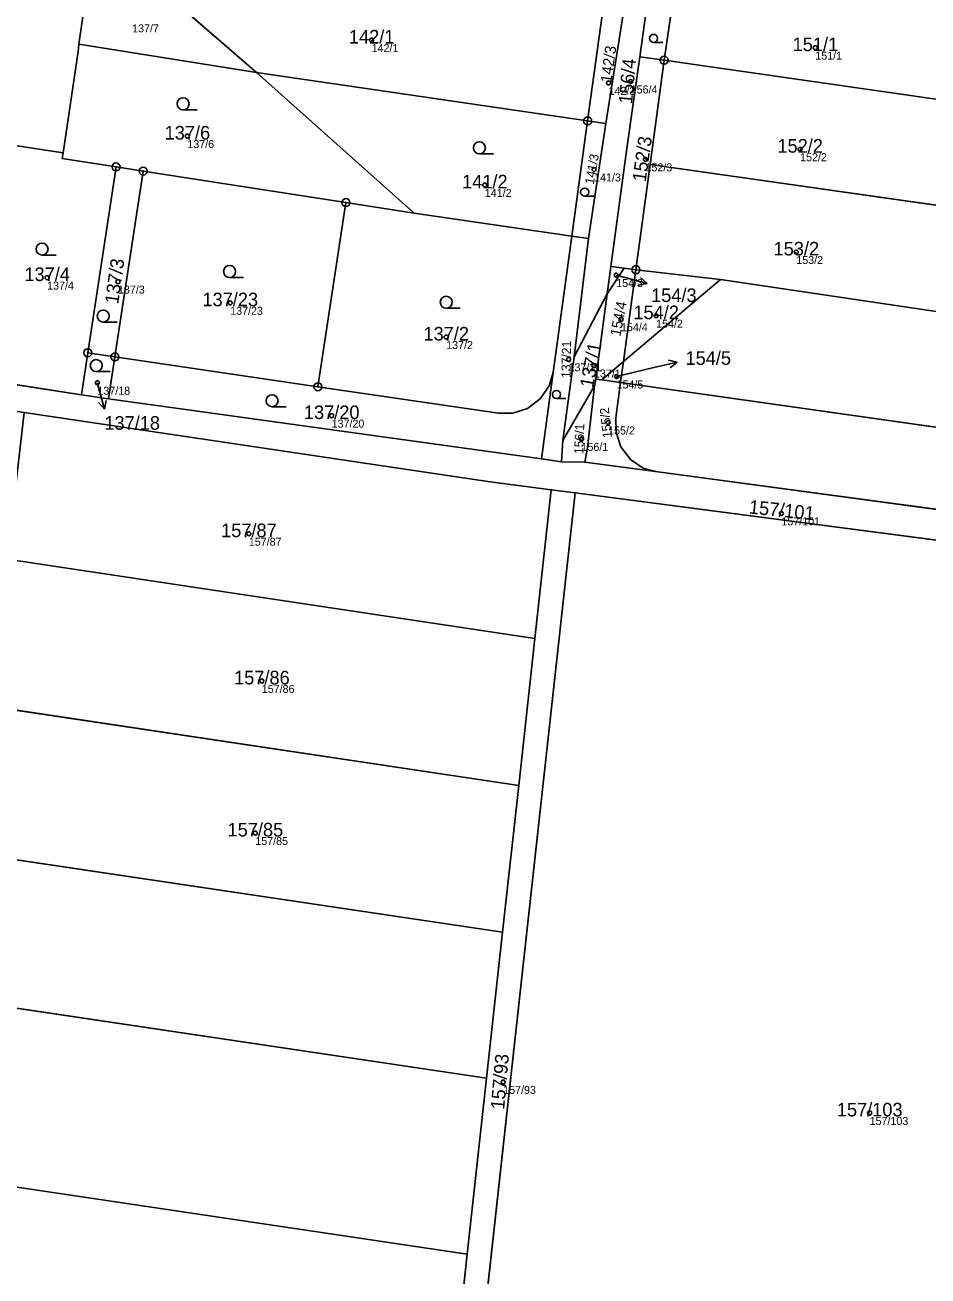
# Model space of a CAD drawing. Extents: x -603967 to -594699, y -1179315 to -1165625.
# Drawn here: x -598435.3 to -598322.4, y -1172798.3 to -1172641.9 of the extents above; entities that cross this region are included whole.
import ezdxf

# ---------------------------------------------------------------- set-up
doc = ezdxf.new("R2010")
doc.units = 0
for name, color, linetype in [('Definiční body', 7, 'Continuous'), ('Hranice parcel', 7, 'Continuous'), ('Parcelní čísla', 7, 'Continuous'), ('Polygon parcely', 7, 'Continuous'), ('Pop  PČ popisy', 7, 'Continuous'), ('Značky bodu BP', 7, 'Continuous'), ('Značky kultur', 7, 'Continuous')]:
    doc.layers.add(name, color=color, linetype=linetype)

msp = doc.modelspace()

# ---------------------------------------------------------------- linework, layer by layer
at = {"layer": 'Definiční body'}
for centre in [(-598391.99, -1172643.83994), (-598336.52, -1172644.78994), (-598362.37, -1172649.18994), (-598359.6, -1172649.01994), (-598415.03, -1172655.83994), (-598357.75, -1172658.74994), (-598338.42, -1172657.47994), (-598364.17, -1172660.00994), (-598377.84, -1172661.94994), (-598338.9, -1172670.32994), (-598432.56, -1172673.52994), (-598423.7, -1172674.02994), (-598361.41, -1172673.20994), (-598409.67, -1172676.67994), (-598360.81, -1172678.72994), (-598356.42, -1172678.28994), (-598382.67, -1172680.95994), (-598367.37, -1172683.74994), (-598364.19, -1172684.51994), (-598426.27, -1172686.66994), (-598361.37, -1172685.88994), (-598396.99, -1172690.77994), (-598362.42, -1172691.63994), (-598365.75, -1172693.68994), (-598340.76, -1172702.99994), (-598407.34, -1172705.53994), (-598405.72, -1172723.93994), (-598406.53, -1172742.94994), (-598375.54, -1172774.05994), (-598329.73, -1172777.93994)]:
    msp.add_circle(centre, 0.25, dxfattribs=at)
at = {"layer": 'Hranice parcel'}
for p, q in [((-598426.71, -1172630.26), (-598406.37, -1172647.87)), ((-598358.46, -1172645.91), (-598356.86, -1172634.46)), ((-598353.75, -1172634.89), (-598355.42, -1172646.35)), ((-598364.98, -1172653.93), (-598362.96, -1172639.21)), ((-598360.39, -1172639.57), (-598362.72, -1172654.26)), ((-598406.37, -1172647.87), (-598428.58, -1172644.33)), ((-598358.46, -1172645.91), (-598360.09, -1172657.4)), ((-598355.42, -1172646.35), (-598358.46, -1172645.91)), ((-598355.42, -1172646.35), (-598357.17, -1172659.37)), ((-598355.42, -1172646.35), (-598319.41, -1172651.51)), ((-598364.98, -1172653.93), (-598406.37, -1172647.87)), ((-598406.37, -1172647.87), (-598386.67, -1172665.48)), ((-598366.97, -1172668.32), (-598364.98, -1172653.93)), ((-598362.72, -1172654.26), (-598364.98, -1172653.93)), ((-598362.72, -1172654.26), (-598364.86, -1172668.62)), ((-598430.55, -1172657.92), (-598436.61, -1172656.99)), ((-598360.09, -1172657.4), (-598362.07, -1172672.12)), ((-598423.94, -1172659.69), (-598427.47, -1172682.92)), ((-598420.55, -1172660.21), (-598423.94, -1172659.69)), ((-598358.94, -1172672.53), (-598357.17, -1172659.37)), ((-598357.17, -1172659.37), (-598313.73, -1172665.56)), ((-598424.08, -1172683.44), (-598420.55, -1172660.21)), ((-598420.55, -1172660.21), (-598395.2, -1172664.15)), ((-598395.2, -1172664.15), (-598398.7, -1172687.17)), ((-598386.67, -1172665.48), (-598395.2, -1172664.15)), ((-598386.67, -1172665.48), (-598366.97, -1172668.32)), ((-598369.29, -1172685.37), (-598366.97, -1172668.32)), ((-598364.86, -1172668.62), (-598366.97, -1172668.32)), ((-598364.86, -1172668.62), (-598366.68, -1172683.42)), ((-598362.07, -1172672.12), (-598362.53, -1172675.55)), ((-598362.53, -1172675.55), (-598360.42, -1172672.36)), ((-598362.07, -1172672.12), (-598360.42, -1172672.36)), ((-598358.94, -1172672.53), (-598360.51, -1172684.01)), ((-598360.42, -1172672.36), (-598358.94, -1172672.53)), ((-598358.94, -1172672.53), (-598348.38, -1172673.77)), ((-598348.38, -1172673.77), (-598360.51, -1172684.01)), ((-598348.38, -1172673.77), (-598315.49, -1172678.65)), ((-598366.68, -1172683.42), (-598362.53, -1172675.55)), ((-598363.95, -1172686.2), (-598362.53, -1172675.55)), ((-598428.27, -1172688.16), (-598427.47, -1172682.92)), ((-598427.47, -1172682.92), (-598424.08, -1172683.44)), ((-598424.88, -1172688.67), (-598424.08, -1172683.44)), ((-598398.7, -1172687.17), (-598424.08, -1172683.44)), ((-598366.68, -1172683.42), (-598368.08, -1172693.89)), ((-598363.22, -1172686.3), (-598360.51, -1172684.01)), ((-598360.51, -1172684.01), (-598360.86, -1172686.63)), ((-598428.27, -1172688.16), (-598441.07, -1172686.19)), ((-598369.29, -1172685.37), (-598370.77, -1172696.19)), ((-598364.11, -1172687.05), (-598363.95, -1172686.2)), ((-598363.95, -1172686.2), (-598363.22, -1172686.3)), ((-598360.86, -1172686.63), (-598363.22, -1172686.3)), ((-598360.86, -1172686.63), (-598361.47, -1172691.06)), ((-598360.86, -1172686.63), (-598274.9, -1172698.81)), ((-598424.88, -1172688.67), (-598428.27, -1172688.16)), ((-598364.11, -1172687.05), (-598368.08, -1172693.89)), ((-598370.77, -1172696.19), (-598424.88, -1172688.67)), ((-598368.08, -1172693.89), (-598368.26, -1172696.54)), ((-598370.77, -1172696.19), (-598368.26, -1172696.54)), ((-598368.26, -1172696.54), (-598365.33, -1172696.58)), ((-598365.33, -1172696.58), (-598356.5, -1172697.77)), ((-598358.03, -1172697.32), (-598356.5, -1172697.77)), ((-598356.5, -1172697.77), (-598281.7, -1172707.81)), ((-598381.45, -1172835.83), (-598366.56, -1172700.44)), ((-598371.58, -1172718.62), (-598369.53, -1172700.04)), ((-598366.56, -1172700.44), (-598369.53, -1172700.04)), ((-598366.56, -1172700.44), (-598273.19, -1172712.63)), ((-598371.58, -1172718.62), (-598437.54, -1172708.73)), ((-598373.59, -1172737), (-598371.58, -1172718.62)), ((-598373.59, -1172737), (-598439.67, -1172727.11)), ((-598375.62, -1172755.34), (-598373.59, -1172737)), ((-598375.62, -1172755.34), (-598441.79, -1172745.48)), ((-598377.62, -1172773.59), (-598504.56, -1172754.7)), ((-598377.62, -1172773.59), (-598375.62, -1172755.34)), ((-598380.04, -1172795.58), (-598377.62, -1172773.59)), ((-598380.04, -1172795.58), (-598492.64, -1172778.82)), ((-598383.06, -1172823.11), (-598380.04, -1172795.58))]:
    msp.add_line(p, q, dxfattribs=at)
for points in [[(-598427.99, -1172640.29), (-598428.16, -1172641.47), (-598428.58, -1172644.33)], [(-598428.58, -1172644.33), (-598428.69, -1172645.28), (-598430.55, -1172657.92)], [(-598423.94, -1172659.69), (-598430.66, -1172658.65), (-598430.55, -1172657.92)], [(-598398.7, -1172687.17), (-598376.12, -1172690.48), (-598374.34, -1172690.48), (-598372.5, -1172689.88), (-598370.9, -1172688.69), (-598369.79, -1172687.06), (-598369.29, -1172685.37)], [(-598365.33, -1172696.58), (-598364.99, -1172694.76), (-598364.11, -1172687.05)], [(-598369.53, -1172700.04), (-598377.46, -1172699.01), (-598435.42, -1172690.36)], [(-598361.47, -1172691.06), (-598361.43, -1172692.84), (-598360.82, -1172694.66), (-598359.62, -1172696.25), (-598358.03, -1172697.32)]]:
    msp.add_lwpolyline(points, dxfattribs=at)
at = {"layer": 'Polygon parcely'}
for points in [[(-598355.28, -1172623.09), (-598354, -1172612.83), (-598352.45, -1172601.73), (-598351.3, -1172595.7), (-598354.22, -1172595.25), (-598355.96, -1172610.07), (-598358.38, -1172624.41), (-598360.39, -1172639.57), (-598362.72, -1172654.26), (-598364.86, -1172668.62), (-598366.68, -1172683.42), (-598362.53, -1172675.55), (-598362.07, -1172672.12), (-598360.09, -1172657.4), (-598358.46, -1172645.91), (-598356.86, -1172634.46)], [(-598490.98, -1172630.62), (-598493.49, -1172630.23), (-598493.67, -1172631.41), (-598496.35, -1172647.82), (-598436.61, -1172656.99), (-598430.55, -1172657.92), (-598428.69, -1172645.28), (-598428.58, -1172644.33), (-598428.16, -1172641.47), (-598427.99, -1172640.29)], [(-598427.99, -1172640.29), (-598428.16, -1172641.47), (-598428.58, -1172644.33), (-598406.37, -1172647.87), (-598426.71, -1172630.26)], [(-598364.98, -1172653.93), (-598362.96, -1172639.21), (-598426.71, -1172630.26), (-598406.37, -1172647.87)], [(-598353.75, -1172634.89), (-598356.86, -1172634.46), (-598358.46, -1172645.91), (-598355.42, -1172646.35)], [(-598353.75, -1172634.89), (-598355.42, -1172646.35), (-598319.41, -1172651.51), (-598298.94, -1172642.4), (-598309.94, -1172640.89)], [(-598360.39, -1172639.57), (-598362.96, -1172639.21), (-598364.98, -1172653.93), (-598362.72, -1172654.26)], [(-598395.2, -1172664.15), (-598386.67, -1172665.48), (-598406.37, -1172647.87), (-598428.58, -1172644.33), (-598428.69, -1172645.28), (-598430.55, -1172657.92), (-598430.66, -1172658.65), (-598423.94, -1172659.69), (-598420.55, -1172660.21)], [(-598358.46, -1172645.91), (-598360.09, -1172657.4), (-598362.07, -1172672.12), (-598360.42, -1172672.36), (-598358.94, -1172672.53), (-598357.17, -1172659.37), (-598355.42, -1172646.35)], [(-598357.17, -1172659.37), (-598313.73, -1172665.56), (-598311.98, -1172652.51), (-598319.41, -1172651.51), (-598355.42, -1172646.35)], [(-598364.98, -1172653.93), (-598406.37, -1172647.87), (-598386.67, -1172665.48), (-598366.97, -1172668.32)], [(-598364.98, -1172653.93), (-598366.97, -1172668.32), (-598364.86, -1172668.62), (-598362.72, -1172654.26)], [(-598428.27, -1172688.16), (-598427.47, -1172682.92), (-598423.94, -1172659.69), (-598430.66, -1172658.65), (-598430.55, -1172657.92), (-598436.61, -1172656.99), (-598441.07, -1172686.19)], [(-598424.08, -1172683.44), (-598420.55, -1172660.21), (-598423.94, -1172659.69), (-598427.47, -1172682.92)], [(-598315.49, -1172678.65), (-598313.73, -1172665.56), (-598357.17, -1172659.37), (-598358.94, -1172672.53), (-598348.38, -1172673.77)], [(-598398.7, -1172687.17), (-598395.2, -1172664.15), (-598420.55, -1172660.21), (-598424.08, -1172683.44)], [(-598398.7, -1172687.17), (-598376.12, -1172690.48), (-598374.34, -1172690.48), (-598372.5, -1172689.88), (-598370.9, -1172688.69), (-598369.79, -1172687.06), (-598369.29, -1172685.37), (-598366.97, -1172668.32), (-598386.67, -1172665.48), (-598395.2, -1172664.15)], [(-598364.86, -1172668.62), (-598366.97, -1172668.32), (-598369.29, -1172685.37), (-598370.77, -1172696.19), (-598368.26, -1172696.54), (-598368.08, -1172693.89), (-598366.68, -1172683.42)], [(-598363.22, -1172686.3), (-598360.51, -1172684.01), (-598358.94, -1172672.53), (-598360.42, -1172672.36), (-598362.53, -1172675.55), (-598363.95, -1172686.2)], [(-598362.53, -1172675.55), (-598360.42, -1172672.36), (-598362.07, -1172672.12)], [(-598358.94, -1172672.53), (-598360.51, -1172684.01), (-598348.38, -1172673.77)], [(-598274.9, -1172698.81), (-598272.85, -1172684.97), (-598315.49, -1172678.65), (-598348.38, -1172673.77), (-598360.51, -1172684.01), (-598360.86, -1172686.63)], [(-598363.95, -1172686.2), (-598362.53, -1172675.55), (-598366.68, -1172683.42), (-598368.08, -1172693.89), (-598364.11, -1172687.05)], [(-598501.79, -1172680.45), (-598435.42, -1172690.36), (-598377.46, -1172699.01), (-598369.53, -1172700.04), (-598366.56, -1172700.44), (-598273.19, -1172712.63), (-598267.08, -1172713.02), (-598266.58, -1172710.18), (-598269.53, -1172709.44), (-598281.7, -1172707.81), (-598356.5, -1172697.77), (-598365.33, -1172696.58), (-598368.26, -1172696.54), (-598370.77, -1172696.19), (-598424.88, -1172688.67), (-598428.27, -1172688.16), (-598441.07, -1172686.19), (-598501.04, -1172676.88)], [(-598424.88, -1172688.67), (-598424.08, -1172683.44), (-598427.47, -1172682.92), (-598428.27, -1172688.16)], [(-598398.7, -1172687.17), (-598424.08, -1172683.44), (-598424.88, -1172688.67), (-598370.77, -1172696.19), (-598369.29, -1172685.37), (-598369.79, -1172687.06), (-598370.9, -1172688.69), (-598372.5, -1172689.88), (-598374.34, -1172690.48), (-598376.12, -1172690.48)], [(-598360.86, -1172686.63), (-598360.51, -1172684.01), (-598363.22, -1172686.3)], [(-598360.86, -1172686.63), (-598363.22, -1172686.3), (-598363.95, -1172686.2), (-598364.11, -1172687.05), (-598364.99, -1172694.76), (-598365.33, -1172696.58), (-598356.5, -1172697.77), (-598358.03, -1172697.32), (-598359.62, -1172696.25), (-598360.82, -1172694.66), (-598361.43, -1172692.84), (-598361.47, -1172691.06)], [(-598356.5, -1172697.77), (-598281.7, -1172707.81), (-598280.42, -1172707.77), (-598278.62, -1172707.16), (-598277.08, -1172705.91), (-598275.97, -1172704.31), (-598275.47, -1172702.5), (-598274.9, -1172698.81), (-598360.86, -1172686.63), (-598361.47, -1172691.06), (-598361.43, -1172692.84), (-598360.82, -1172694.66), (-598359.62, -1172696.25), (-598358.03, -1172697.32)], [(-598364.11, -1172687.05), (-598368.08, -1172693.89), (-598368.26, -1172696.54), (-598365.33, -1172696.58), (-598364.99, -1172694.76)], [(-598437.54, -1172708.73), (-598371.58, -1172718.62), (-598369.53, -1172700.04), (-598377.46, -1172699.01), (-598435.42, -1172690.36), (-598437.44, -1172707.81)], [(-598387.22, -1172888.4), (-598385.83, -1172875.74), (-598384.37, -1172862.43), (-598381.45, -1172835.83), (-598366.56, -1172700.44), (-598369.53, -1172700.04), (-598371.58, -1172718.62), (-598373.59, -1172737), (-598375.62, -1172755.34), (-598377.62, -1172773.59), (-598380.04, -1172795.58), (-598383.06, -1172823.11), (-598386.27, -1172852.23), (-598388.21, -1172869.98), (-598391.58, -1172900.59), (-598392.59, -1172909.8), (-598389.59, -1172910.18)], [(-598381.45, -1172835.83), (-598284.95, -1172847.74), (-598270.45, -1172715.99), (-598273.19, -1172712.63), (-598366.56, -1172700.44)], [(-598439.51, -1172725.76), (-598439.67, -1172727.11), (-598373.59, -1172737), (-598371.58, -1172718.62), (-598437.54, -1172708.73)], [(-598373.59, -1172737), (-598439.67, -1172727.11), (-598441.79, -1172745.48), (-598375.62, -1172755.34)], [(-598509.23, -1172735.44), (-598504.56, -1172754.7), (-598377.62, -1172773.59), (-598375.62, -1172755.34), (-598441.79, -1172745.48)], [(-598380.04, -1172795.58), (-598377.62, -1172773.59), (-598504.56, -1172754.7), (-598504.46, -1172755.12), (-598492.64, -1172778.82)], [(-598380.04, -1172795.58), (-598492.64, -1172778.82), (-598477.56, -1172809.04), (-598383.06, -1172823.11)]]:
    msp.add_lwpolyline(points, close=True, dxfattribs=at)
at = {"layer": 'Pop  PČ popisy'}
for p, q in [((-598361.41, -1172673.21), (-598360.45, -1172673.47)), ((-598360.45, -1172673.47), (-598357.551, -1172674.247)), ((-598357.551, -1172674.247), (-598358.389, -1172673.504)), ((-598357.551, -1172674.247), (-598358.648, -1172674.471)), ((-598361.37, -1172685.89), (-598356.71, -1172684.77)), ((-598356.71, -1172684.77), (-598353.786, -1172684.095)), ((-598353.786, -1172684.095), (-598354.874, -1172683.832)), ((-598353.786, -1172684.095), (-598354.649, -1172684.808)), ((-598426.27, -1172686.67), (-598426.17, -1172687.07)), ((-598426.17, -1172687.07), (-598425.393, -1172689.969)), ((-598425.393, -1172689.969), (-598426.136, -1172689.131)), ((-598425.393, -1172689.969), (-598425.169, -1172688.872))]:
    msp.add_line(p, q, dxfattribs=at)
at = {"layer": 'Značky bodu BP'}
for centre, radius in [((-598355.42, -1172646.34988), 0.5), ((-598355.42, -1172646.34988), 0.0303), ((-598364.98, -1172653.92988), 0.5), ((-598364.98, -1172653.92988), 0.0303), ((-598423.94, -1172659.68988), 0.5), ((-598423.94, -1172659.68988), 0.0303), ((-598420.55, -1172660.20988), 0.5), ((-598420.55, -1172660.20988), 0.0303), ((-598395.2, -1172664.14988), 0.5), ((-598395.2, -1172664.14988), 0.0303), ((-598358.94, -1172672.52988), 0.5), ((-598358.94, -1172672.52988), 0.0303), ((-598427.47, -1172682.91988), 0.5), ((-598427.47, -1172682.91988), 0.0303), ((-598424.08, -1172683.43988), 0.5), ((-598424.08, -1172683.43988), 0.0303), ((-598398.7, -1172687.16988), 0.5), ((-598398.7, -1172687.16988), 0.0303)]:
    msp.add_circle(centre, radius, dxfattribs=at)
at = {"layer": 'Značky kultur'}
for p, q in [((-598356.735, -1172644.12), (-598355.563, -1172644.12)), ((-598415.553, -1172652.55), (-598413.803, -1172652.55)), ((-598378.513, -1172658.05), (-598376.763, -1172658.05)), ((-598365.355, -1172663.34), (-598364.183, -1172663.34)), ((-598433.193, -1172670.7), (-598431.443, -1172670.7)), ((-598409.753, -1172673.51), (-598408.003, -1172673.51)), ((-598382.663, -1172677.36), (-598380.913, -1172677.36)), ((-598425.543, -1172679.07), (-598423.793, -1172679.07)), ((-598426.413, -1172685.26), (-598424.663, -1172685.26)), ((-598404.443, -1172689.66), (-598402.693, -1172689.66)), ((-598368.875, -1172688.64), (-598367.703, -1172688.64))]:
    msp.add_line(p, q, dxfattribs=at)
for centre, radius in [((-598356.73521, -1172643.61737), 0.5025), ((-598415.55286, -1172651.79981), 0.75), ((-598378.51286, -1172657.29981), 0.75), ((-598365.35521, -1172662.83737), 0.5025), ((-598433.19286, -1172669.94981), 0.75), ((-598409.75286, -1172672.75981), 0.75), ((-598382.66286, -1172676.60981), 0.75), ((-598425.54286, -1172678.31981), 0.75), ((-598426.41286, -1172684.50981), 0.75), ((-598404.44286, -1172688.90981), 0.75), ((-598368.87521, -1172688.13737), 0.5025)]:
    msp.add_circle(centre, radius, dxfattribs=at)

# ---------------------------------------------------------------- texts
at = {"layer": 'Definiční body'}
for s, p in [('137/7', (-598421.93, -1172642.869)), ('142/1', (-598391.99, -1172645.329)), ('151/1', (-598336.52, -1172646.279)), ('142/3', (-598362.37, -1172650.679)), ('156/4', (-598359.6, -1172650.509)), ('137/6', (-598415.03, -1172657.329)), ('152/2', (-598338.42, -1172658.969)), ('152/3', (-598357.75, -1172660.239)), ('141/3', (-598364.17, -1172661.499)), ('141/2', (-598377.84, -1172663.439)), ('153/2', (-598338.9, -1172671.819)), ('137/4', (-598432.56, -1172675.019)), ('154/3', (-598361.41, -1172674.699)), ('137/3', (-598423.7, -1172675.519)), ('137/23', (-598409.67, -1172678.169)), ('154/2', (-598356.42, -1172679.779)), ('154/4', (-598360.81, -1172680.219)), ('137/2', (-598382.67, -1172682.449)), ('137/21', (-598367.37, -1172685.239)), ('137/1', (-598364.19, -1172686.009)), ('154/5', (-598361.37, -1172687.379)), ('137/18', (-598426.27, -1172688.159)), ('137/20', (-598396.99, -1172692.269)), ('155/2', (-598362.42, -1172693.129)), ('156/1', (-598365.75, -1172695.179)), ('157/101', (-598340.76, -1172704.489)), ('157/87', (-598407.34, -1172707.029)), ('157/86', (-598405.72, -1172725.429)), ('157/85', (-598406.53, -1172744.439)), ('157/93', (-598375.54, -1172775.549)), ('157/103', (-598329.73, -1172779.429))]:
    msp.add_text(s, height=0.999996, dxfattribs=at).set_placement(p)
at = {"layer": 'Parcelní čísla'}
for s, p in [('142/1', (-598394.826, -1172644.265)), ('151/1', (-598339.356, -1172645.215)), ('137/6', (-598417.866, -1172656.265)), ('152/2', (-598341.256, -1172657.905)), ('141/2', (-598380.676, -1172662.375)), ('153/2', (-598341.736, -1172670.755)), ('137/4', (-598435.396, -1172673.955)), ('137/23', (-598413.136, -1172677.105)), ('154/3', (-598357.05, -1172676.575)), ('154/2', (-598359.256, -1172678.715)), ('137/2', (-598385.506, -1172681.385)), ('154/5', (-598352.746, -1172684.425)), ('137/20', (-598400.456, -1172691.205)), ('137/18', (-598425.4, -1172692.535)), ('157/87', (-598410.806, -1172705.965)), ('157/86', (-598409.186, -1172724.365)), ('157/85', (-598409.996, -1172743.375)), ('157/103', (-598333.826, -1172778.365))]:
    msp.add_text(s, height=1.699998, dxfattribs=at).set_placement(p)
for s, height, rotation, p in [('142/3', 1.386996, 82, (-598362.026, -1172649.238)), ('156/4', 1.699998, 85, (-598359.423, -1172651.882)), ('152/3', 1.699998, 82, (-598357.723, -1172661.617)), ('141/3', 1.138998, 80, (-598364.219, -1172661.93)), ('137/3', 1.699998, 82, (-598423.673, -1172676.897)), ('154/4', 1.308996, 79, (-598360.905, -1172680.936)), ('137/21', 1.138998, 89, (-598367.125, -1172686.077)), ('137/1', 1.699998, 79, (-598364.313, -1172687.385)), ('155/2', 1.138998, 96, (-598361.938, -1172693.5)), ('156/1', 1.14, 87.9999972, (-598365.531, -1172695.6)), ('157/101', 1.699998, 354, (-598344.878, -1172702.994)), ('157/93', 1.699998, 85, (-598375.418, -1172777.55))]:
    msp.add_text(s, height=height, rotation=rotation, dxfattribs=at).set_placement(p)

doc.saveas('drawing.dxf')
